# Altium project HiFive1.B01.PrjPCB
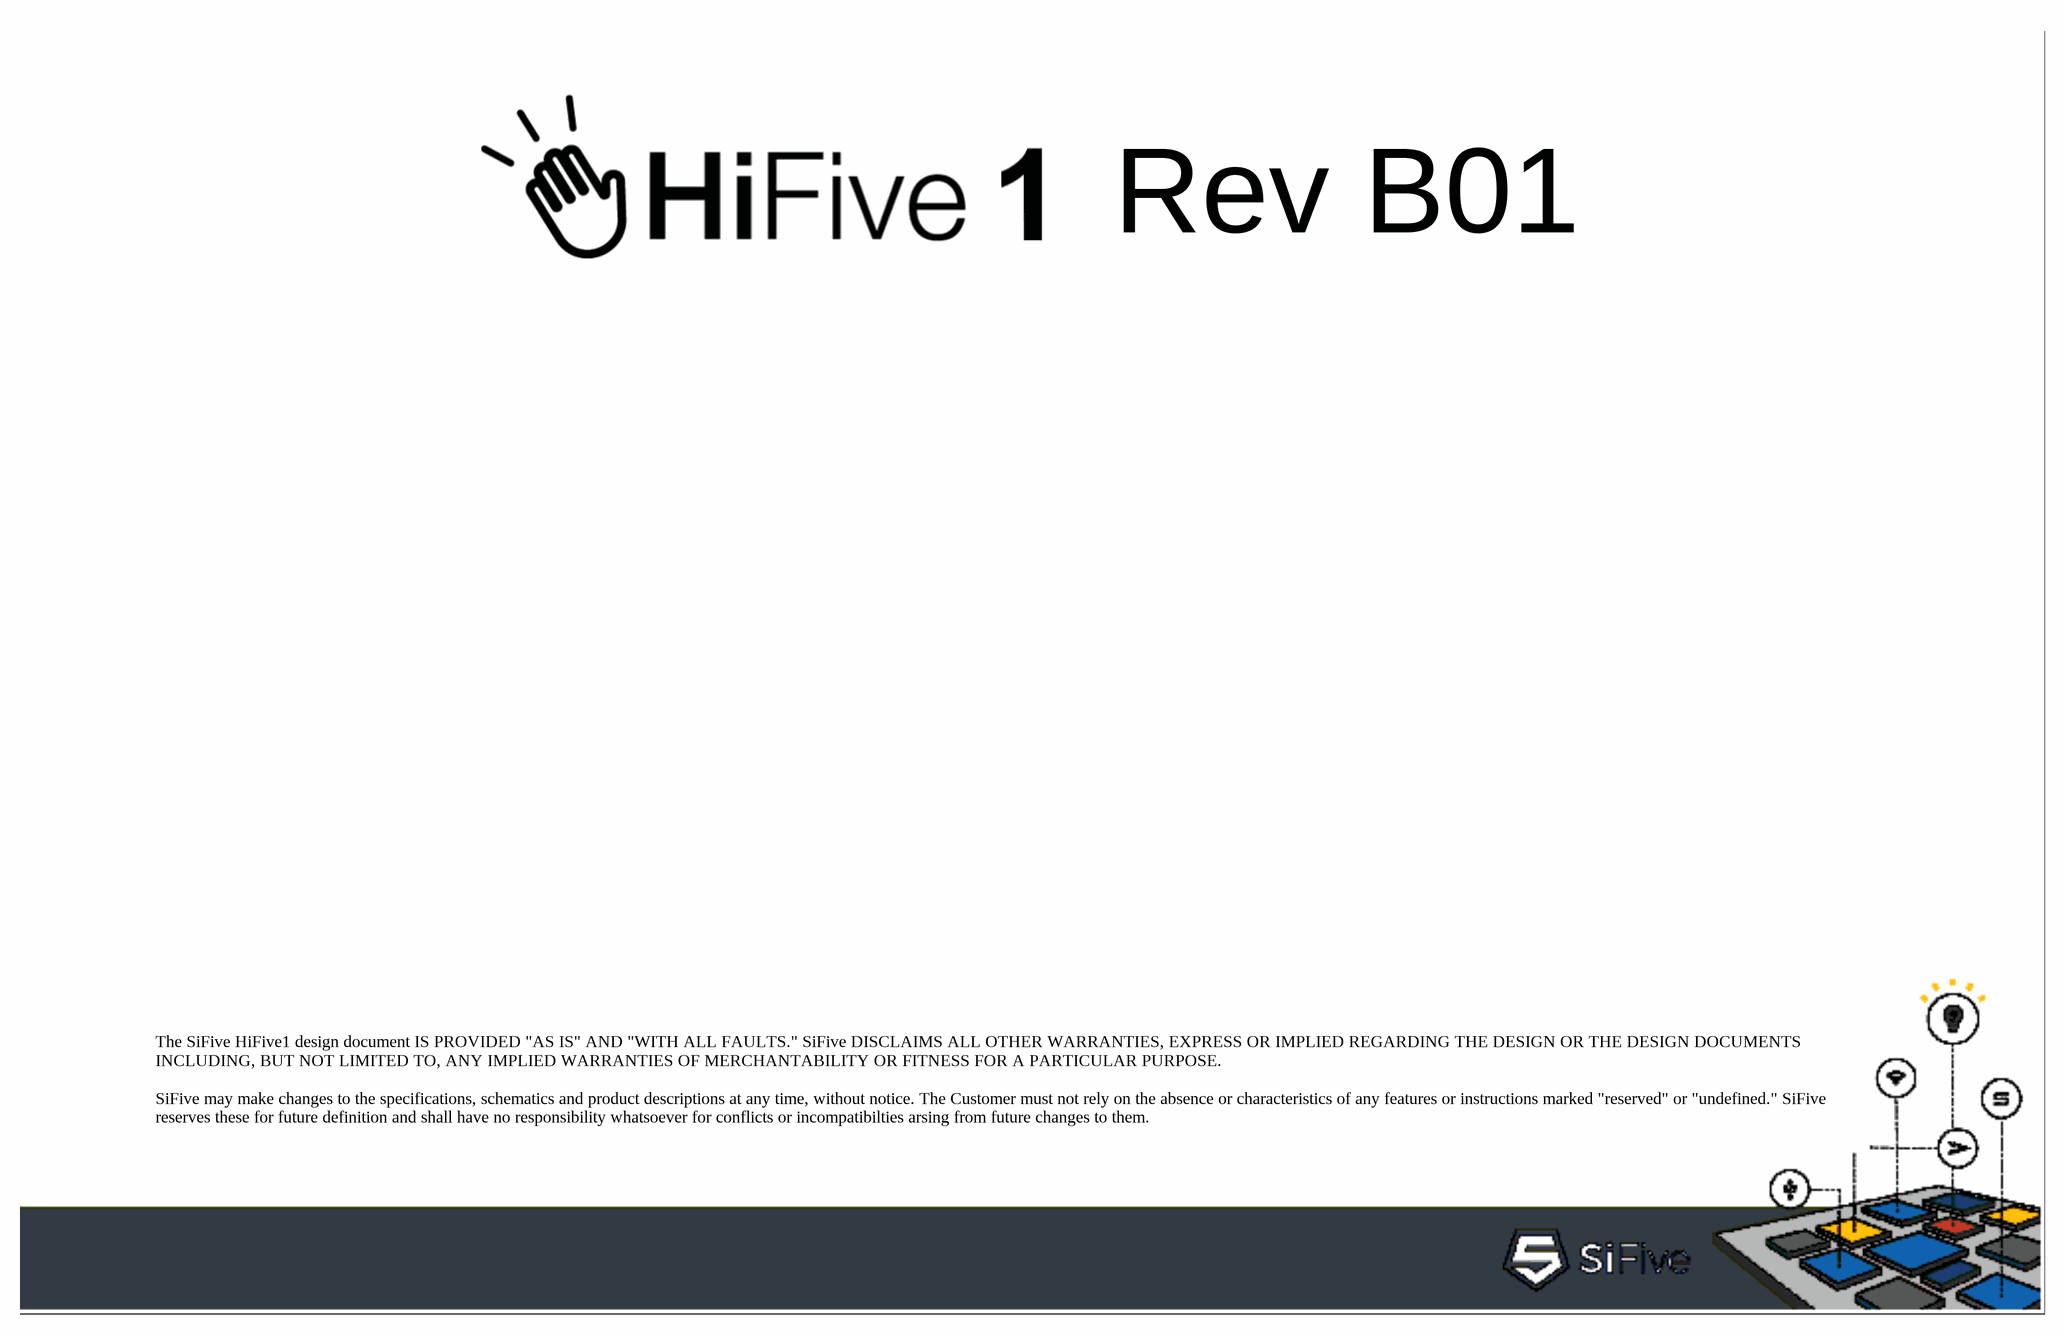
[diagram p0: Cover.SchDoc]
5 sheets, 109 parts. Net scope: flat (ports and power ports of the same name join across sheets).
Board file: HiFive1.B01.PcbDoc
Sheets:
  Cover.SchDoc
  Power.SchDoc
  Freedom_E310.SchDoc
  Debug.SchDoc
  WiFi_BT.SchDoc

## Sheet Cover.SchDoc
size B; Revision: B01; SheetNumber: 1; SheetTotal: 5

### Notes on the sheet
- Rev B01
- The SiFive HiFive1 design document IS PROVIDED "AS IS" AND "WITH ALL FAULTS." SiFive DISCLAIMS ALL OTHER WARRANTIES, EXPRESS OR IMPLIED REGARDING THE DESIGN OR THE DESIGN DOCUMENTS INCLUDING, BUT NOT LIMITED TO, ANY IMPLIED WARRANTIES OF MERCHANTABILITY OR FITNESS FOR A PARTICULAR PURPOSE.
  SiFive may make changes to the specifications, schematics and product descriptions at any time, without notice. The Customer must not rely on the absence or characteristics of any features or instructions marked "reserved" or "undefined." SiFive reserves these for future definition and shall have no responsibility whatsoever for conflicts or incompatibilties arsing from future changes to them.

## Sheet Power.SchDoc: Power Supply
size B; Revision: B01; SheetNumber: 2; SheetTotal: 5; ProjectCodeName: HiFive1
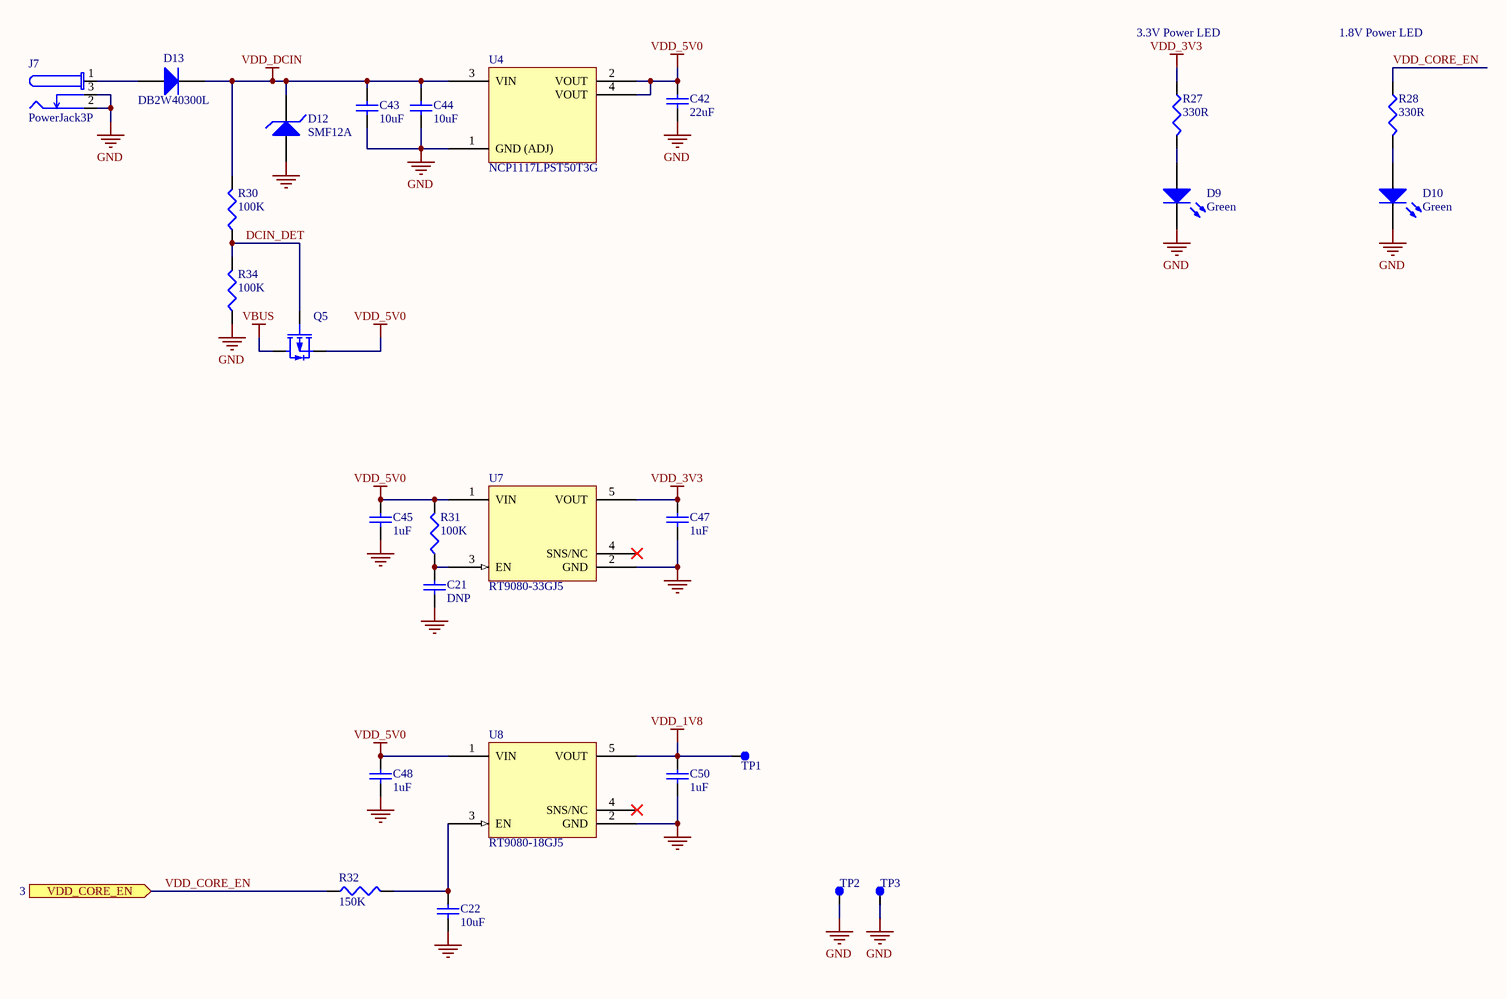
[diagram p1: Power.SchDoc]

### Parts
C21  DNP  [C0603]  (no BOM)
C22  10uF  [C0603]
C42  22uF  [C0805]
C43  10uF  [C0805]
C44  10uF  [C0805]
C45  1uF  [C0603]
C47  1uF  [C0603]
C48  1uF  [C0603]
C50  1uF  [C0603]
D9  Green  [LED0805]
D10  Green  [LED0805]
D12  SMF12A  [SOD-123FL]
D13  DB2W40300L  [SOD-123FL]
J7  PowerJack3P  [PJ-102AH]
Q5  MOSFET-P_SOT23  [SOT-23B]  (value not drawn)
R27  330R  [R0402]
R28  330R  [R0402]
R30  100K  [R0402]
R31  100K  [R0402]
R32  150K  [R0402]
R34  100K  [R0402]
TP1  Testpoint  [Testpoint_SMT]  (value not drawn)  (no BOM)
TP2  Testpoint  [Testpoint_SMT]  (value not drawn)  (no BOM)
TP3  Testpoint  [Testpoint_SMT]  (value not drawn)  (no BOM)
U4  NCP1117LPST50T3G  [SOT223P700X180-4N]
U7  RT9080-33GJ5  [TSOT23-5]
U8  RT9080-18GJ5  [TSOT23-5]

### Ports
VDD_CORE_EN (in, see 3)

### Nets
GND: C21.2 C22.2 C42.2 C43.2 C44.2 C45.2 C47.2 C48.2 C50.2 D9.1(K) D10.1(K) D12.2(A) J7.2 J7.3 R34.1 TP2.1 TP3.1 U4.1(GND_(ADJ)) U7.2(GND) U8.2(GND)
VBUS: Q5.3(D)
VDD_1V8: C50.1 TP1.1 U8.5(VOUT)
VDD_3V3: C47.1 R27.1 U7.5(VOUT)
VDD_5V0: C42.1 C45.1 C48.1 Q5.2(S) R31.2 U4.2(VOUT) U4.4(VOUT) U7.1(VIN) U8.1(VIN)
VDD_DCIN: C43.1 C44.1 D12.1(K) D13.1(K) R30.2 U4.3(VIN)
DCIN_DET: Q5.1(G) R30.1 R34.2
VDD_CORE_EN: R28.1 R32.1 ; port VDD_CORE_EN
NetC21_1: C21.1 R31.1 U7.3(EN)
NetC22_1: C22.1 R32.2 U8.3(EN)
NetD9_2: D9.2(A) R27.2
NetD10_2: D10.2(A) R28.2
NetD13_2: D13.2(A) J7.1

Not connected (* = marked no-connect by the designer): U7 4(SNS/NC)*; U8 4(SNS/NC)*

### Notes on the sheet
- 3.3V Power LED
- 1.8V Power LED

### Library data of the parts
C21 = C0100007: 10µF 6.3V Ceramic Capacitor X5R 0603; Manufacturer: Murata Electronics; Manufacturer PN: GRM188R60J106ME47J; Value: 10uF; Tolerance: ±10%
C22 = C0100033: CAP CER 10UF 10V X5R 0603; Manufacturer: Murata Electronics; Manufacturer PN: GRM188R61A106KE69J; Tolerance: ±10%
C42 = C0100010: 22µF 6.3V Ceramic Capacitor X5R 0805; Manufacturer: Murata Electronics; Manufacturer PN: GRM21BR60J226ME39L; Tolerance: ±20%
C43 C44 = C0100015: 10µF ±10% 25V Ceramic Capacitor X5R 0805; Manufacturer: Murata Electronics; Manufacturer PN: GRM21BR61E106KA73L
C45 C47 C48 C50 = C0100006: 1µF 16V Ceramic Capacitor X5R 0603; Manufacturer: Murata Electronics; Manufacturer PN: GRM188R61C105KA93D; Tolerance: ±10%
D9 D10 = E0000001: Green 570nm LED Indication - Discrete 2.2V 0805; Manufacturer: OSRAM Opto Semiconductors Inc; Manufacturer PN: LG R971-KN-1
D12 = D0000002: TVS DIODE 12VWM 19.9VC SOD123; Manufacturer: Littelfuse Inc; Voltage Reverse Standoff: 12V; Voltage Breakdown: 13.3V; Voltage Reverse Clamping: 19.9V
D13 = D0000006: Diode Schottky 40V 3A (DC) Surface Mount; Manufacturer: Panasonic Electronic Components; Voltage Forward: 0.54V@3A
J7 = J0000003: Power Barrel Connector Jack 2.00mm ID (0.079"), 5.50mm OD (0.217") Through Hole, Right Angle; Manufacturer: CUI Inc
Q5 = Q0000005: MOSFET P-CH 20V 4.2A SOT23; Manufacturer: Diodes Inc; Manufacturer PN: DMG2305UX-13; Value: P-Channel
R27 R28 = R0000026: RES SMD 330 OHM 1% 1/16W 0402; Manufacturer: Yageo; Manufacturer PN: RC0402FR-07330RL; Power Rating: 0.063W
R30 R31 R34 = R0000012: RES SMD 100K OHM 1% 1/16W 0402; Manufacturer: Yageo; Manufacturer PN: RC0402FR-07100KL; Power Rating: 0.063W
R32 = R0000055: RES SMD 150K OHM 1% 1/16W 0402; Manufacturer: Yageo; Manufacturer PN: RC0402FR-07150KL; Power Rating: 0.063W
TP1-TP3 = M0000002: Test Point SMT
U4 = U0000051: IC REG LINEAR 5V 1A SOT223; Manufacturer: ON Semiconductor
U7 = U0000066: Linear Voltage Regulator IC Positive Fixed 1 Output 3.3V 600mA TSOT-23-5; Manufacturer: Richtek USA
U8 = U0000065: Linear Voltage Regulator IC Positive Fixed 1 Output 1.8V 600mA TSOT-23-5; Manufacturer: Richtek USA

## Sheet Freedom_E310.SchDoc: Freedom E310
size B; Revision: B01; SheetNumber: 3; SheetTotal: 5; ProjectCodeName: HiFive1
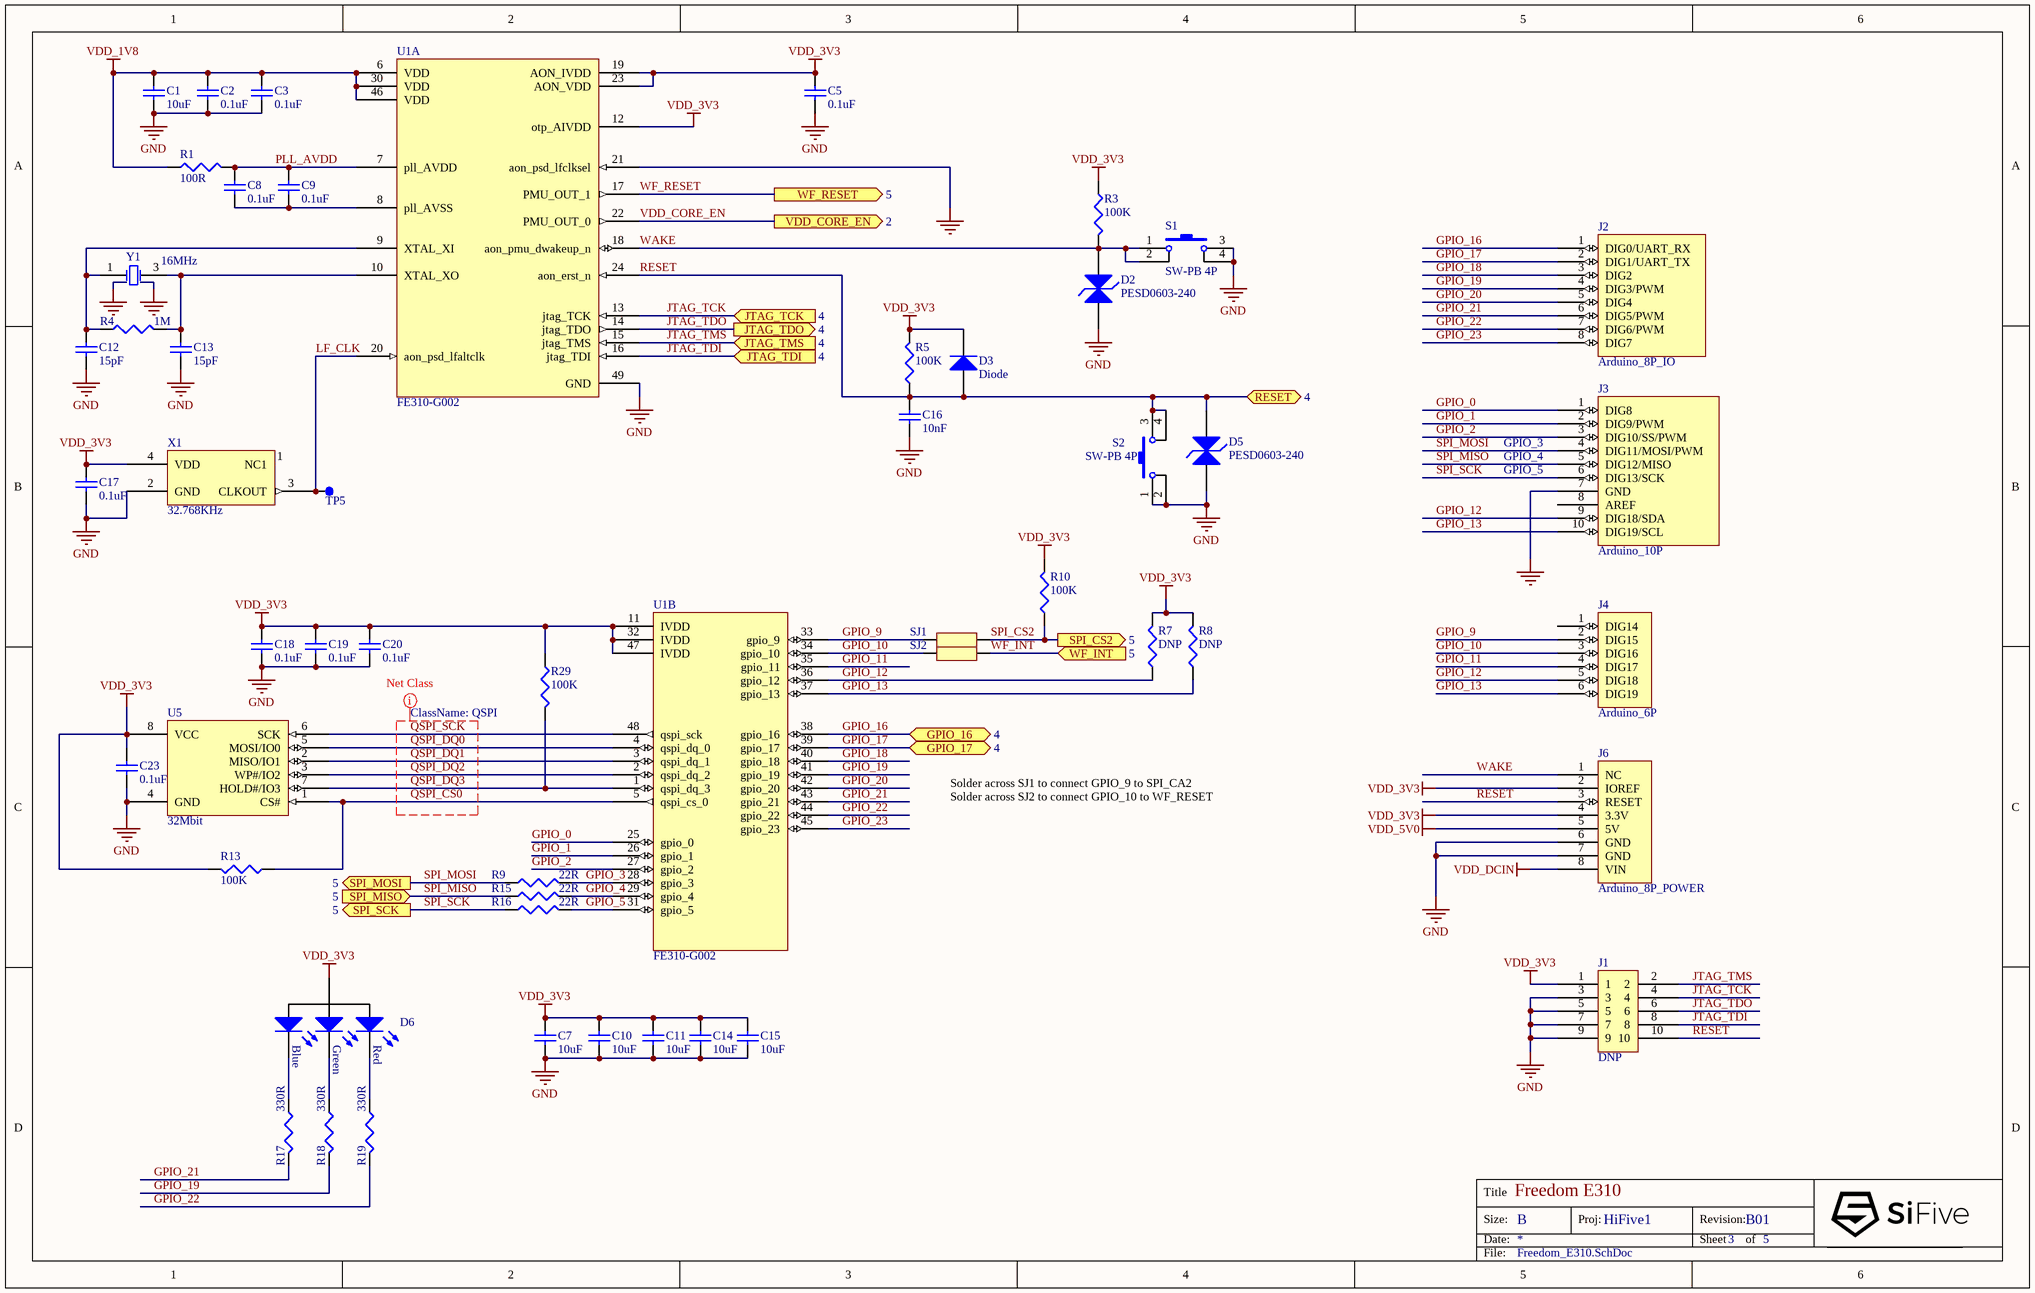
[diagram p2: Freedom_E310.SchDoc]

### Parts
C1  10uF  [C0603]
C2  0.1uF  [C0402]
C3  0.1uF  [C0402]
C5  0.1uF  [C0402]
C7  10uF  [C0603]
C8  0.1uF  [C0402]
C9  0.1uF  [C0402]
C10  10uF  [C0603]
C11  10uF  [C0603]
C12  15pF  [C0402]
C13  15pF  [C0402]
C14  10uF  [C0603]
C15  10uF  [C0603]
C16  10nF  [C0402]
C17  0.1uF  [C0402]
C18  0.1uF  [C0402]
C19  0.1uF  [C0402]
C20  0.1uF  [C0402]
C23  0.1uF  [C0402]
D2  PESD0603-240  [R0603]
D3  Diode  [SOD523]
D5  PESD0603-240  [R0603]
D6  LED_RGB_LTST-C19HE1WT  [LED0606]  (value not drawn)
J1  DNP  [CNC_3221-10-0300-00]  (no BOM)
J2  Arduino_8P_IO  [Arduino_8P_IO]
J3  Arduino_10P  [Arduino_10P]
J4  Arduino_6P  [Arduino_6P]
J6  Arduino_8P_POWER  [Arduino_8P_POWER]
R1  100R  [R0402]
R3  100K  [R0402]
R4  1M  [R0402]
R5  100K  [R0402]
R7  DNP  [R0402]  (no BOM)
R8  DNP  [R0402]  (no BOM)
R9  22R  [R0402]
R10  100K  [R0402]
R13  100K  [R0402]
R15  22R  [R0402]
R16  22R  [R0402]
R17  330R  [R0402]
R18  330R  [R0402]
R19  330R  [R0402]
R29  100K  [R0402]
S1  SW-PB 4P  [PTS645_SMT]
S2  SW-PB 4P  [PTS645_SMT]
SJ1  Solder Jumper  [SJ0805]  (value not drawn)  (no BOM)
SJ2  Solder Jumper  [SJ0805]  (value not drawn)  (no BOM)
TP5  Testpoint  [Testpoint_SMT]  (value not drawn)  (no BOM)
U1  FE310-G002  [QFN48_40P600X600X90_HS-49]  (parts A,B of 2)
U5  32Mbit  [SOIC127P790X216-8N]
X1  32.768KHz  [SiTime2012]
Y1  16MHz  [X3225]

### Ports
GPIO_16 (bidir, see 4), GPIO_17 (bidir, see 4), JTAG_TCK (in, see 4), JTAG_TDI (in, see 4), JTAG_TDO (out, see 4), JTAG_TMS (in, see 4), RESET (bidir, see 4), SPI_CS2 (out, see 5), SPI_MISO (in, see 5), SPI_MOSI (out, see 5), SPI_SCK (out, see 5), VDD_CORE_EN (out, see 2), WF_INT (in, see 5), WF_RESET (out, see 5)

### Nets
GND: C1.2 C2.1 C3.1 C5.1 C7.2 C10.2 C11.2 C12.2 C13.2 C14.2 C15.2 C16.2 C17.1 C18.1 C19.1 C20.1 C23.1 D2.2 D5.2 J1.3 J1.5 J1.7 J1.9 J3.7(GND) J6.6(GND) J6.7(GND) S1.3 S1.4 S2.1 S2.2 U1.21(aon_psd_lfclksel) U1.49(GND) U5.4(GND) X1.2(GND) Y1.2(NC1) Y1.4(NC2)
VDD_1V8: C1.1 C2.2 C3.2 R1.1 U1.6(VDD) U1.30(VDD) U1.46(VDD)
VDD_3V3: C5.2 C7.1 C10.1 C11.1 C14.1 C15.1 C17.2 C18.2 C19.2 C20.2 C23.2 D3.1(K) D6.4(A) J1.1 J6.2(IOREF) J6.4(3.3V) R3.1 R5.2 R7.2 R8.2 R10.2 R13.2 R29.1 U1.11(IVDD) U1.12(otp_AIVDD) U1.19(AON_IVDD) U1.23(AON_VDD) U1.32(IVDD) U1.47(IVDD) U5.8(VCC) X1.4(VDD)
VDD_5V0: J6.5(5V)
VDD_DCIN: J6.8(VIN)
GPIO_0: J3.1(DIG8) U1.25(gpio_0)
GPIO_1: J3.2(DIG9/PWM) U1.26(gpio_1)
GPIO_2: J3.3(DIG10/SS/PWM) U1.27(gpio_2)
GPIO_3: R9.2 U1.28(gpio_3)
GPIO_4: R15.2 U1.29(gpio_4)
GPIO_5: R16.2 U1.31(gpio_5)
GPIO_9: J4.2(DIG15) SJ1.1 U1.33(gpio_9)
GPIO_10: J4.3(DIG16) SJ2.1 U1.34(gpio_10)
GPIO_11: J4.4(DIG17) U1.35(gpio_11)
GPIO_12: J3.9(DIG18/SDA) J4.5(DIG18) R7.1 U1.36(gpio_12)
GPIO_13: J3.10(DIG19/SCL) J4.6(DIG19) R8.1 U1.37(gpio_13)
GPIO_16: J2.1(DIG0/UART_RX) U1.38(gpio_16) ; port GPIO_16
GPIO_17: J2.2(DIG1/UART_TX) U1.39(gpio_17) ; port GPIO_17
GPIO_18: J2.3(DIG2) U1.40(gpio_18)
GPIO_19: J2.4(DIG3/PWM) R18.2 U1.41(gpio_19)
GPIO_20: J2.5(DIG4) U1.42(gpio_20)
GPIO_21: J2.6(DIG5/PWM) R17.2 U1.43(gpio_21)
GPIO_22: J2.7(DIG6/PWM) R19.2 U1.44(gpio_22)
GPIO_23: J2.8(DIG7) U1.45(gpio_23)
JTAG_TCK: J1.4 U1.13(jtag_TCK) ; port JTAG_TCK
JTAG_TDI: J1.8 U1.16(jtag_TDI) ; port JTAG_TDI
JTAG_TDO: J1.6 U1.14(jtag_TDO) ; port JTAG_TDO
JTAG_TMS: J1.2 U1.15(jtag_TMS) ; port JTAG_TMS
LF_CLK: TP5.1 U1.20(aon_psd_lfaltclk) X1.3(CLKOUT)
PLL_AVDD: C8.2 C9.2 R1.2 U1.7(pll_AVDD)
QSPI_CS0: R13.1 U1.5(qspi_cs_0) U5.1(CS#)
QSPI_DQ0: U1.4(qspi_dq_0) U5.5(MOSI/IO0)
QSPI_DQ1: U1.3(qspi_dq_1) U5.2(MISO/IO1)
QSPI_DQ2: U1.2(qspi_dq_2) U5.3(WP#/IO2)
QSPI_DQ3: R29.2 U1.1(qspi_dq_3) U5.7(HOLD#/IO3)
QSPI_SCK: U1.48(qspi_sck) U5.6(SCK)
RESET: C16.1 D3.2(A) D5.1 J1.10 J6.3(RESET) R5.1 S2.3 S2.4 U1.24(aon_erst_n) ; port RESET
SPI_CS2: R10.1 SJ1.2 ; port SPI_CS2
SPI_MISO: J3.5(DIG12/MISO) R15.1 ; port SPI_MISO
SPI_MOSI: J3.4(DIG11/MOSI/PWM) R9.1 ; port SPI_MOSI
SPI_SCK: J3.6(DIG13/SCK) R16.1 ; port SPI_SCK
VDD_CORE_EN: U1.22(PMU_OUT_0) ; port VDD_CORE_EN
WAKE: D2.1 J6.1(NC) R3.2 S1.1 S1.2 U1.18(aon_pmu_dwakeup_n)
WF_INT: SJ2.2 ; port WF_INT
WF_RESET: U1.17(PMU_OUT_1) ; port WF_RESET
NetC8_1: C8.1 C9.1 U1.8(pll_AVSS)
NetC12_1: C12.1 R4.1 U1.9(XTAL_XI) Y1.1(OSC1)
NetC13_1: C13.1 R4.2 U1.10(XTAL_XO) Y1.3(OSC2)
NetD6_1: D6.1(RedK) R19.1
NetD6_2: D6.2(GreenK) R18.1
NetD6_3: D6.3(BlueK) R17.1

Not connected (* = marked no-connect by the designer): J3 8(AREF); J4 1(DIG14); X1 1(NC1)

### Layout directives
net class QSPI: QSPI_CS0, QSPI_DQ0, QSPI_DQ1, QSPI_DQ2, QSPI_DQ3, QSPI_SCK

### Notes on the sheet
- GPIO_3
- GPIO_4
- GPIO_5
- Solder across SJ1 to connect GPIO_9 to SPI_CA2
  Solder across SJ2 to connect GPIO_10 to WF_RESET

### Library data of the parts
C1 C7 C10 C11 C14 C15 = C0100033: as C22 on sheet Power
C2 C3 C5 C8 C9 C17-C20 C23 = C0100004: 0.10µF 16V Ceramic Capacitor X7R 0402; Manufacturer: Samsung Electro-Mechanics; Manufacturer PN: CL05B104KO5NFNC; Tolerance: ±10%
C12 C13 = C0100038: CAP CER 15PF 50V C0G/NPO 0402; Manufacturer: Yageo; Manufacturer PN: CC0402JRNPO9BN150; Type: C0G; Tolerance: ±5%
C16 = C0100037: CAP CER 10000PF 50V X7R 0402; Manufacturer: Samsung Electro-Mechanics; Manufacturer PN: CL05B103KB5VPNC; Tolerance: ±10%
D2 D5 = D0000013: TVS Diode 24VWM  45VClamp; Manufacturer: Littlefuse; Voltage Reverse Standoff: 24V
D3 = D0000001: Diode Standard 80V 125mA Surface Mount SOD-523; Manufacturer: Diodes Incorporated; Value: 1N4148WT-7
D6 = E0000005: Red, Green, Blue (RGB) 624nm Red, 525nm Green, 470nm Blue LED Indication - Discrete 1.8V Red, 2.8V Green, 2.8V Blue 0606; Manufacturer: Lite-on Inc.
J1 = J0000049: Connector Header Surface Mount 10 position 0.050" (1.27mm); Manufacturer: CNC Tech; Manufacturer PN: 3221-10-0300-00
J2 = J0000005: Arduino 8 Pin I/O Connector; Manufacturer: Sullins Connector Solutions; Manufacturer PN: PPTC081LFBN-RC
J3 = J0000007: Arduino 10 Pin Connector; Manufacturer: Sullins Connector Solutions; Manufacturer PN: PPTC101LFBN-RC
J4 = J0000004: Arduino 6 Pin Connector; Manufacturer: Sullins Connector Solutions; Manufacturer PN: PPTC061LFBN-RC
J6 = J0000006: Arduino 8 Pin Power Connector; Manufacturer: Sullins Connector Solutions; Manufacturer PN: PPTC081LFBN-RC
R1 = R0000020: RES SMD 100 OHM 1% 1/16W 0402; Manufacturer: Yageo; Manufacturer PN: RC0402FR-07100RL; Power Rating: 0.063W
R3 R5 R10 R13 R29 = R0000012: as R30 on sheet Power
R4 = R0000021: RES SMD 1M OHM 1% 1/16W 0402; Manufacturer: Yageo; Manufacturer PN: RC0402FR-071ML; Power Rating: 0.063W
R7 R8 = R0000025: RES SMD 2K OHM 1% 1/16W 0402; Manufacturer: Yageo; Manufacturer PN: RC0402FR-072KL; Power Rating: 0.063W
R9 R15 R16 = R0000022: RES SMD 22 OHM 1% 1/16W 0402; Manufacturer: Yageo; Manufacturer PN: RC0402FR-0722RL; Power Rating: 0.063W
R17-R19 = R0000026: as R27 on sheet Power
S1 = M0000004: Blue Tactile Switch SPST-NO Top Actuated Surface Mount; Manufacturer: C & K Components; Manufacturer PN: PTS645SM43SMTR92 LFS
S2 = M0000003: Red Tactile Switch SPST-NO Top Actuated Surface Mount; Manufacturer: C & K Components; Manufacturer PN: PTS645SK43SMTR92 LFS
SJ1 SJ2 = M0000009: Solder Bridge 0805; Manufacturer: None
TP5 = M0000002: Test Point SMT
U1 = U0000050: SiFive Freedom E310 Microcontroller
U5 = U0000019: IC FLASH 32MBIT 133MHZ 8SOIC 2.3 V ~ 3.6 V; Manufacturer: ISSI; Manufacturer PN: IS25LP032D-JBLE
X1 = X0000014: 32.768kHz LVCMOS MEMS (Silicon) Oscillator Surface Mount 1.2 V ~ 3.63 V 1.3µA; Manufacturer: SiTime; Manufacturer PN: SIT1533AI-H4-DCC-32.768E; Frequency Stability: ±100 ppm
Y1 = X0000015: 16MHz ±10ppm Crystal 9pF 60 Ohm; Manufacturer: Epson; Manufacturer PN: TSX-3225 16.0000MF18X-AC0; Frequency Stability: ±18ppm; ESR: 60 Ohms

## Sheet Debug.SchDoc: USB to UART and JTAG
size B; Revision: B01; SheetNumber: 4; SheetTotal: 5; ProjectCodeName: HiFive1
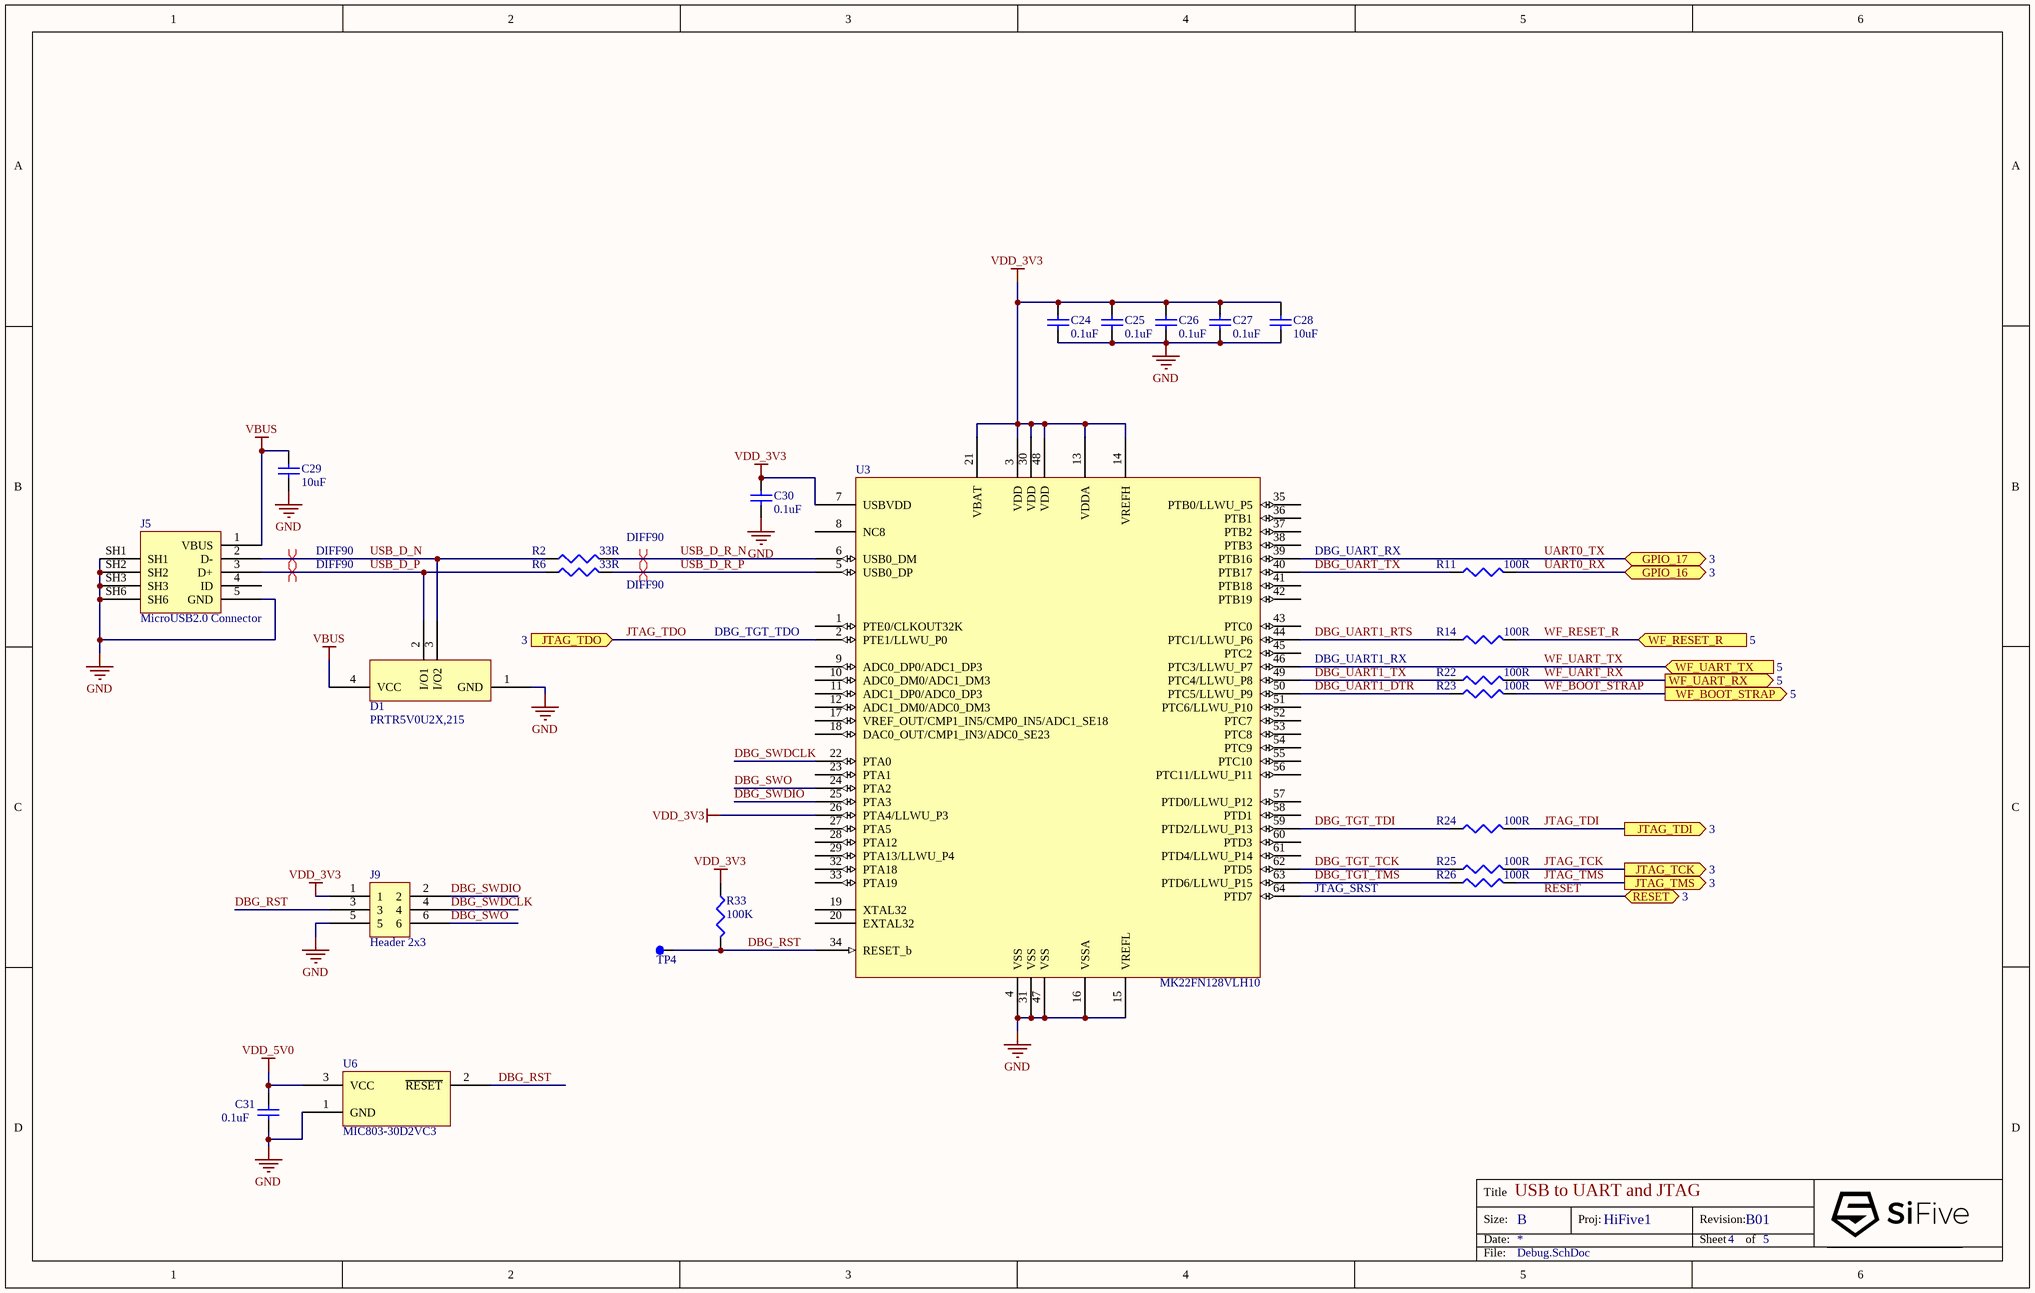
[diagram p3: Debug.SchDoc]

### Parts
C24  0.1uF  [C0402]
C25  0.1uF  [C0402]
C26  0.1uF  [C0402]
C27  0.1uF  [C0402]
C28  10uF  [C0603]
C29  10uF  [C0603]
C30  0.1uF  [C0402]
C31  0.1uF  [C0402]
D1  PRTR5V0U2X,215  [SOT-143B]
J5  MicroUSB2.0 Connector  [FCI_10118194-0001LF]
J9  Header 2x3  [TC2030-IDC-FP]  (no BOM)
R2  33R  [R0402]
R6  33R  [R0402]
R11  100R  [R0402]
R14  100R  [R0402]
R22  100R  [R0402]
R23  100R  [R0402]
R24  100R  [R0402]
R25  100R  [R0402]
R26  100R  [R0402]
R33  100K  [R0402]
TP4  Testpoint  [Testpoint_SMT]  (value not drawn)  (no BOM)
U3  MK22FN128VLH10  [LQFP-64]
U6  MIC803-30D2VC3  [SOT65P210X110-3N_A]

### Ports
GPIO_16 (bidir, see 3), GPIO_17 (bidir, see 3), JTAG_TCK (out, see 3), JTAG_TDI (out, see 3), JTAG_TDO (in, see 3), JTAG_TMS (out, see 3), RESET (bidir, see 3), WF_BOOT_STRAP (out, see 5), WF_RESET_R (in, see 5), WF_UART_RX (out, see 5), WF_UART_TX (in, see 5)

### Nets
GND: C24.2 C25.2 C26.2 C27.2 C28.1 C29.1 C30.2 C31.2 D1.1(GND) J5.5(GND) J5.SH1 J5.SH2 J5.SH3 J5.SH6 J9.5 U3.4(VSS) U3.15(VREFL) U3.16(VSSA) U3.31(VSS) U3.47(VSS) U6.1(GND)
VBUS: C29.2 D1.4(VCC) J5.1(VBUS)
VDD_3V3: C24.1 C25.1 C26.1 C27.1 C28.2 C30.1 J9.1 R33.1 U3.3(VDD) U3.7(USBVDD) U3.13(VDDA) U3.14(VREFH) U3.21(VBAT) U3.26(PTA4/LLWU_P3) U3.30(VDD) U3.48(VDD)
VDD_5V0: C31.1 U6.3(VCC)
DBG_RST: J9.3 R33.2 TP4.1 U3.34(RESET_b) U6.2(~{RESET})
DBG_SWDCLK: J9.4 U3.22(PTA0)
DBG_SWDIO: J9.2 U3.25(PTA3)
DBG_SWO: J9.6 U3.24(PTA2)
DBG_TGT_TCK: R25.1 U3.62(PTD5)
DBG_TGT_TDI: R24.1 U3.59(PTD2/LLWU_P13)
DBG_TGT_TMS: R26.1 U3.63(PTD6/LLWU_P15)
DBG_UART1_DTR: R23.1 U3.50(PTC5/LLWU_P9)
DBG_UART1_RTS: R14.1 U3.44(PTC1/LLWU_P6)
DBG_UART1_TX: R22.1 U3.49(PTC4/LLWU_P8)
DBG_UART_TX: R11.1 U3.40(PTB17)
JTAG_TCK: R25.2 ; port JTAG_TCK
JTAG_TDI: R24.2 ; port JTAG_TDI
JTAG_TDO: U3.2(PTE1/LLWU_P0) ; port JTAG_TDO
JTAG_TMS: R26.2 ; port JTAG_TMS
RESET: U3.64(PTD7) ; port RESET
UART0_RX: R11.2 ; port GPIO_16  [project net GPIO_16]
UART0_TX: U3.39(PTB16) ; port GPIO_17  [project net GPIO_17]
USB_D_N: D1.3(I/O2) J5.2(D-) R2.1
USB_D_P: D1.2(I/O1) J5.3(D+) R6.1
USB_D_R_N: R2.2 U3.6(USB0_DM)
USB_D_R_P: R6.2 U3.5(USB0_DP)
WF_BOOT_STRAP: R23.2 ; port WF_BOOT_STRAP
WF_RESET_R: R14.2 ; port WF_RESET_R
WF_UART_RX: R22.2 ; port WF_UART_RX
WF_UART_TX: U3.46(PTC3/LLWU_P7) ; port WF_UART_TX

Not connected (* = marked no-connect by the designer): J5 4(ID); U3 1(PTE0/CLKOUT32K) 8(NC8) 9(ADC0_DP0/ADC1_DP3) 10(ADC0_DM0/ADC1_DM3) 11(ADC1_DP0/ADC0_DP3) 12(ADC1_DM0/ADC0_DM3) 17(VREF_OUT/CMP1_IN5/CMP0_IN5/ADC1_SE18) 18(DAC0_OUT/CMP1_IN3/ADC0_SE23) 19(XTAL32) 20(EXTAL32) 23(PTA1) 27(PTA5) 28(PTA12) 29(PTA13/LLWU_P4) 32(PTA18) 33(PTA19) 35(PTB0/LLWU_P5) 36(PTB1) 37(PTB2) 38(PTB3) 41(PTB18) 42(PTB19) 43(PTC0) 45(PTC2) 51(PTC6/LLWU_P10) 52(PTC7) 53(PTC8) 54(PTC9) 55(PTC10) 56(PTC11/LLWU_P11) 57(PTD0/LLWU_P12) 58(PTD1) 60(PTD3) 61(PTD4/LLWU_P14)

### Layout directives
differential pair; net class DIFF90: USB_D_N, USB_D_P, USB_D_R_N, USB_D_R_P

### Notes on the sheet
- DBG_UART_RX
- DBG_TGT_TDO
- DBG_UART1_RX
- JTAG_SRST

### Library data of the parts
C24-C27 C30 C31 = C0100004: as C2 on sheet Freedom_E310
C28 C29 = C0100033: as C22 on sheet Power
D1 = D0000012: TVS DIODE 5.5V SOT143B; Manufacturer: Nexperia; Voltage Breakdown: 6V
J5 = J0000048: USB - micro B USB 2.0 Receptacle Connector 5 Position Surface Mount, Right Angle, Horizontal; Manufacturer: Amphenol FCI; Manufacturer PN: 10118194-0001LF
J9 = J0000045: 2x3 Connector, Small footprint, no legs, no component; Manufacturer: Tag Connect
R2 R6 = R0000044: RES SMD 33 OHM 1% 1/16W 0402; Manufacturer: Yageo; Manufacturer PN: RC0402FR-0733RL; Power Rating: 0.063W
R11 R14 R22-R26 = R0000020: as R1 on sheet Freedom_E310
R33 = R0000012: as R30 on sheet Power
TP4 = M0000002: Test Point SMT
U3 = U0000058: ARM® Cortex®-M4 Kinetis K20 Microcontroller IC 32-Bit 100MHz 128KB (128K x 8) FLASH 64-LQFP (10x10); Manufacturer: NXP USA Inc
U6 = U0000076: IC MPU SUPERVISOR SC70-3; Manufacturer: Microchip

## Sheet WiFi_BT.SchDoc: WiFi and Bluetooth
size B; Revision: B01; SheetNumber: 5; SheetTotal: 5; ProjectCodeName: HiFive1
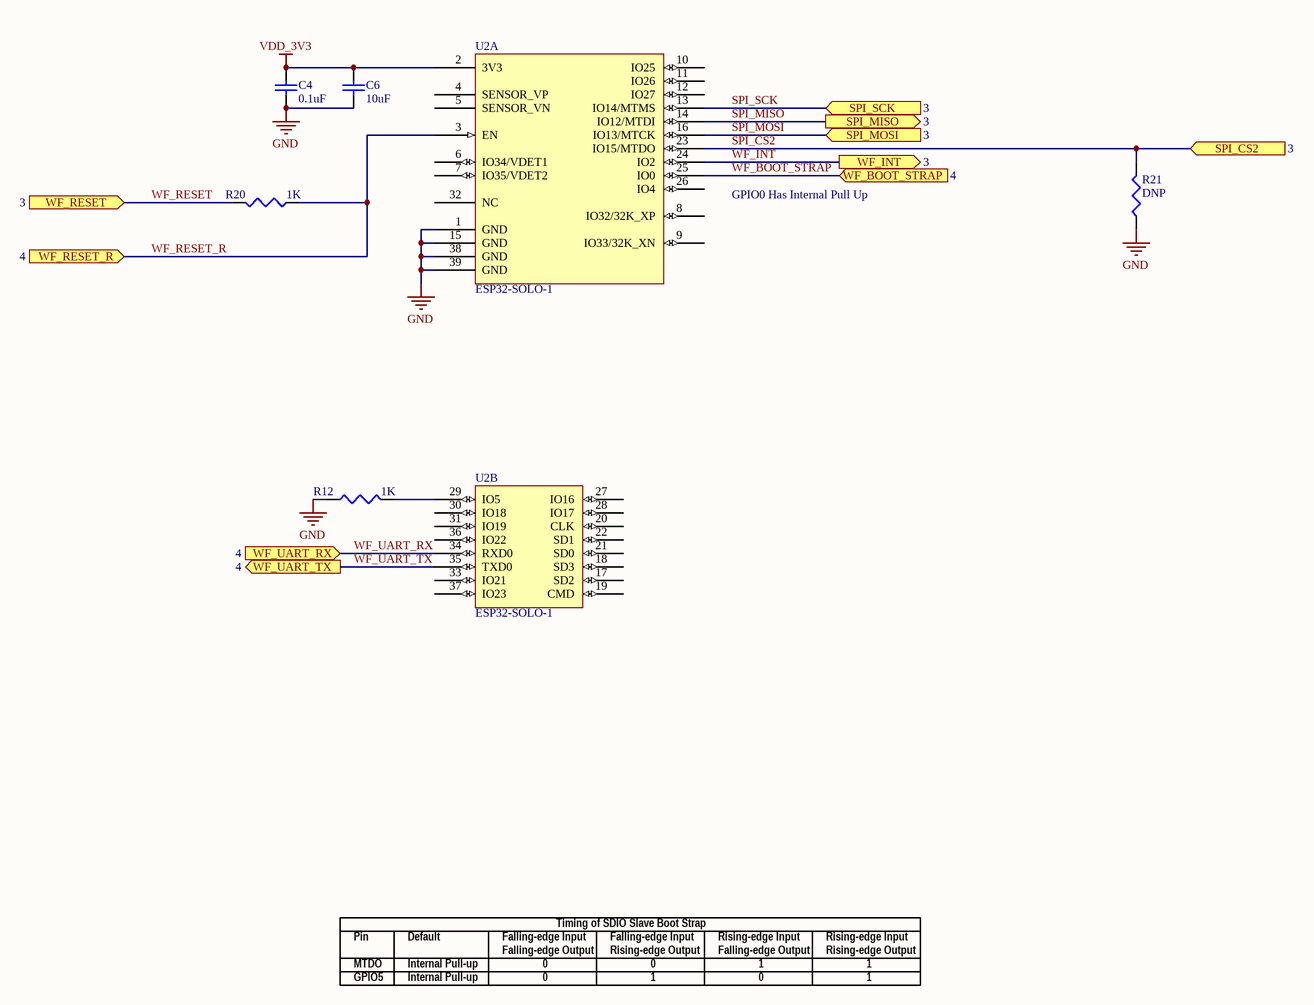
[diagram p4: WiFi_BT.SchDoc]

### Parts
C4  0.1uF  [C0402]
C6  10uF  [C0603]
R12  1K  [R0402]
R20  1K  [R0402]
R21  DNP  [R0402]  (no BOM)
U2  ESP32-SOLO-1  [ESP-WROOM-32]  (parts A,B of 2)

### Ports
SPI_CS2 (in, see 3), SPI_MISO (out, see 3), SPI_MOSI (in, see 3), SPI_SCK (in, see 3), WF_BOOT_STRAP (in, see 4), WF_INT (out, see 3), WF_RESET (in, see 3), WF_RESET_R (in, see 4), WF_UART_RX (in, see 4), WF_UART_TX (out, see 4)

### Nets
GND: C4.1 C6.2 R12.1 R21.1 U2.1(GND) U2.15(GND) U2.38(GND) U2.39(GND)
VDD_3V3: C4.2 C6.1 U2.2(3V3)
SPI_CS2: R21.2 U2.23(IO15/MTDO) ; port SPI_CS2
SPI_MISO: U2.14(IO12/MTDI) ; port SPI_MISO
SPI_MOSI: U2.16(IO13/MTCK) ; port SPI_MOSI
SPI_SCK: U2.13(IO14/MTMS) ; port SPI_SCK
WF_BOOT_STRAP: U2.25(IO0) ; port WF_BOOT_STRAP
WF_INT: U2.24(IO2) ; port WF_INT
WF_RESET: R20.2 ; port WF_RESET
WF_RESET_R: R20.1 U2.3(EN) ; port WF_RESET_R
WF_UART_RX: U2.34(RXD0) ; port WF_UART_RX
WF_UART_TX: U2.35(TXD0) ; port WF_UART_TX
NetR12_2: R12.2 U2.29(IO5)

Not connected (* = marked no-connect by the designer): U2 4(SENSOR_VP) 5(SENSOR_VN) 6(IO34/VDET1) 7(IO35/VDET2) 8(IO32/32K_XP) 9(IO33/32K_XN) 10(IO25) 11(IO26) 12(IO27) 17(SD2) 18(SD3) 19(CMD) 20(CLK) 21(SD0) 22(SD1) 26(IO4) 27(IO16) 28(IO17) 30(IO18) 31(IO19) 32(NC) 33(IO21) 36(IO22) 37(IO23)

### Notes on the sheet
- GPIO0 Has Internal Pull Up
- Timing of SDIO Slave Boot Strap
- Pin
- MTDO
- GPIO5
- Default
- Internal Pull-up
- Falling-edge Input
- Falling-edge Output
- 0
- Rising-edge Output
- 1
- Rising-edge Input

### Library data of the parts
C4 = C0100004: as C2 on sheet Freedom_E310
C6 = C0100033: as C22 on sheet Power
R12 R20 R21 = R0000019: RES SMD 1K OHM 1% 1/16W 0402; Manufacturer: Yageo; Manufacturer PN: RC0402FR-071KL; Power Rating: 0.063W
U2 = U0000061: WiFi 802.11n + BT4.2 Chipset Module Single Core with PCB Antenna 18mmx25.5mm; Manufacturer: Espressif Systems

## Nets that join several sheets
GND: Power (20 pins), Freedom_E310 (36 pins), Debug (21 pins), WiFi_BT (8 pins)
VBUS: Power (Q5.3), Debug (C29.2 D1.4 J5.1)
VDD_1V8: Power (C50.1 TP1.1 U8.5), Freedom_E310 (7 pins)
VDD_3V3: Power (C47.1 R27.1 U7.5), Freedom_E310 (31 pins), Debug (16 pins), WiFi_BT (C4.2 C6.1 U2.2)
VDD_5V0: Power (9 pins), Freedom_E310 (J6.5), Debug (C31.1 U6.3)
VDD_DCIN: Power (6 pins), Freedom_E310 (J6.8)
GPIO_16: Freedom_E310 (J2.1 U1.38), Debug (R11.2)
GPIO_17: Freedom_E310 (J2.2 U1.39), Debug (U3.39)
JTAG_TCK: Freedom_E310 (J1.4 U1.13), Debug (R25.2)
JTAG_TDI: Freedom_E310 (J1.8 U1.16), Debug (R24.2)
JTAG_TDO: Freedom_E310 (J1.6 U1.14), Debug (U3.2)
JTAG_TMS: Freedom_E310 (J1.2 U1.15), Debug (R26.2)
RESET: Freedom_E310 (9 pins), Debug (U3.64)
SPI_CS2: Freedom_E310 (R10.1 SJ1.2), WiFi_BT (R21.2 U2.23)
SPI_MISO: Freedom_E310 (J3.5 R15.1), WiFi_BT (U2.14)
SPI_MOSI: Freedom_E310 (J3.4 R9.1), WiFi_BT (U2.16)
SPI_SCK: Freedom_E310 (J3.6 R16.1), WiFi_BT (U2.13)
VDD_CORE_EN: Power (R28.1 R32.1), Freedom_E310 (U1.22)
WF_BOOT_STRAP: Debug (R23.2), WiFi_BT (U2.25)
WF_INT: Freedom_E310 (SJ2.2), WiFi_BT (U2.24)
WF_RESET: Freedom_E310 (U1.17), WiFi_BT (R20.2)
WF_RESET_R: Debug (R14.2), WiFi_BT (R20.1 U2.3)
WF_UART_RX: Debug (R22.2), WiFi_BT (U2.34)
WF_UART_TX: Debug (U3.46), WiFi_BT (U2.35)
